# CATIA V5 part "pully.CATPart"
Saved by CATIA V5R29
Part number: pully
Source: Unknown
Bounding box of the stored display mesh (mm): x -20 to 20, y -7 to 7, z -20 to 20
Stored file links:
  C:\가치같이\SmartFactory_BoxErectorConveyor\pully.CATPart
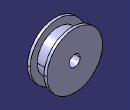
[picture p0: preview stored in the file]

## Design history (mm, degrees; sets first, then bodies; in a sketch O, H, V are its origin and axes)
Body1 (main body)
  Solid1 "PartBody": solid without history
